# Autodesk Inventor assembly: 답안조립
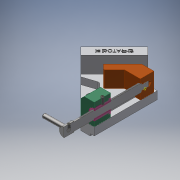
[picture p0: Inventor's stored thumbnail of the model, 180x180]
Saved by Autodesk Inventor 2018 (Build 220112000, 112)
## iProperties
Created: 2019-04
Part Number: 답안조립
Document SubType Name: Assembly
Designer: Administrator
Author: Administrator
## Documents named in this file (11)
- C:\Users\expoc\Desktop\490408V1009\답안조립.iam
- C:\Users\expoc\Desktop\490408V1009\본체.ipt
- C:\Users\expoc\Desktop\490408V1009\리드스크류.ipt
- C:\Users\expoc\Desktop\490408V1009\서포트.ipt
- C:\Users\expoc\Desktop\490408V1009\조.ipt
- C:\Users\expoc\Desktop\490408V1009\부시.ipt
- C:\Users\expoc\Desktop\490408V1009\핸들.ipt
- C:\Users\expoc\Desktop\490408V1009\멈춤나사 M4x10.ipt
- C:\Users\expoc\Desktop\490408V1009\평행 핀 2.5x24.ipt
- C:\Users\expoc\Desktop\490408V1009\볼트 M4x16.ipt
- C:\Users\expoc\Desktop\490408V1009\멈춤나사 M4x5.ipt
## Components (1 placed, 1 different names)
1. 핸들:1 — Mate:13
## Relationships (1: Mate 1)
- Mate:13: 핸들:1
